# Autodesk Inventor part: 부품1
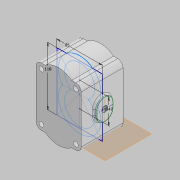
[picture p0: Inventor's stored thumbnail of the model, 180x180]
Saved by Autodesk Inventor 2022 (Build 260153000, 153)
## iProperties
Created: 2023-06
Part Number: 부품1
Material: 일반
Document SubType Name: Modeling
Designer: PC-04
Density: 1 g/cm^3
Appearance: 기본값
Author: PC-04
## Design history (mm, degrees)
sketch "스케치1"
  geometry: L1 (42.5, -55)-(-42.5, -55); L2 (-42.5, -55)-(-42.5, 55); L3 (-42.5, 55)-(42.5, 55); L4 (42.5, 55)-(42.5, -55); L5 (42.5, -55)-(-42.5, 55); L6 (-42.5, -55)-(42.5, 55); L7 (0, 55)-(0, -55); L8 (-42.5, 0)-(42.5, 0); A1 r 28.5 centre (0, 23.5) between (16.125, 0) and (-16.125, 0); A2 r 28.5 centre (0, -23.5) between (-16.125, 0) and (16.125, 0); A3 r 40 centre (0, 23.5) between (32.369, 0) and (-32.369, 0); A4 r 40 centre (0, -23.5) between (-32.369, 0) and (32.369, 0); 5 further points
  constraints: 16 end point, 8 point on circle, 6 midpoint, 4 centre point, 2 coincident, 2 parallel, 2 point on line, 1 horizontal, 1 perpendicular, 1 symmetric about line
  dimensions: "d1" = 85 distance of L2.end L3.end; "d2" = 110 distance of L1.end L2.end; "d7" = 47 diameter of A1.centre L8
extrude "돌출1" new body sketch "스케치1" stored distance "d10" = 79; taper "d11" = 0 deg
fillet "모깎기1" dims "d22" = 10
sketch "스케치5"
  geometry: L1 (32.5, -45)-(-32.5, -45); L2 (-32.5, -45)-(-32.5, 45); L3 (-32.5, 45)-(32.5, 45); L4 (32.5, 45)-(32.5, -45); L5 (32.5, -45)-(-32.5, 45); L6 (-32.5, -45)-(32.5, 45); 1 further point
  constraints: 12 end point, 2 midpoint, 2 parallel, 1 horizontal, 1 perpendicular
  dimensions: "d23" = 65 distance of L2.end L3.end; "d24" = 90 distance of L1.end L2.end
hole "구멍1" sketch "스케치5" at (32.5, -45), (-32.5, -45), (-32.5, 45), (32.5, 45) diameter "d25" = 9; stored, may be unused: countersink angle "d29" = 90 deg, drill point angle "d31" = 118 deg; dims "d26" = 10, "d27" = 4, "d28" = 2, "d30" = 40
sketch "스케치6"
  geometry: L1 (0, 0)-(79, 0) reference; L2 (0, 0)-(79, 0) reference; L3 (39.5, -90)-(39.5, 0); L4 (0, 0)-(79, 0) reference; L5 (39.5, -50)-(39.5, -40); L6 (54.5, -50)-(54.5, -40); L7 (24.5, -40)-(24.5, -50); L8 (79, 0)-(79, -90) reference; L9 (0, -90)-(79, -90) reference; L10 (0, -90)-(0, 0) reference; L11 (79, 0)-(79, -90) reference; L12 (0, -90)-(79, -90) reference; L13 (0, -90)-(0, 0) reference; A1 r 15 centre (39.5, -50) between (24.5, -50) and (54.5, -50); A2 r 15 centre (39.5, -40) between (54.5, -40) and (24.5, -40); 4 further points; 1 other entity
  constraints: 10 end point, 4 point on circle, 4 tangent, 3 midpoint, 2 centre point, 1 parallel, 1 point on line, 2 other
  dimensions: "d32" = 30 distance between parallel lines of L6 L7; "d33" = 10 distance of L5.start L5.end
extrude "돌출6" join sketch "스케치6" distance "d34" = 5; taper "d35" = 0 deg
sketch "스케치8"
  geometry: L1 (24.5, -40)-(24.5, -50) reference; L2 (24.5, -45)-(54.5, -45); L3 (54.5, -40)-(54.5, -50) reference; L4 (39.5, -25)-(39.5, -65); A1 r 15 centre (39.5, -40) between (54.5, -40) and (24.5, -40) reference; A2 r 15 centre (39.5, -50) between (24.5, -50) and (54.5, -50) reference; 2 further points
  constraints: 4 end point, 3 midpoint, 2 point on circle, 1 perpendicular
hole "구멍3" sketch "스케치8" diameter "d43" = 10.5; stored, may be unused: countersink angle "d49" = 90 deg, drill point angle "d51" = 0 deg; dims "d44" = 11, "d45" = 0.62479, "d46" = 10.589, "d47" = 4, "d48" = 2, "d50" = 17.5
fillet "모깎기2" dims "d52" = 3
node "작업 평면2"
node "솔리드1"
mirror "미러1"
node "절단 모서리 투영3"
node "절단 모서리 투영4"
feature "A9D066F2-1C7D-4E18-AEED-F7BC21143FA4" dims "d25" = 9, "d26" = 10, "d27" = 4, "d28" = 2, "d29" = 90 deg, "d30" = 40, "d31" = 118 deg
other parameters: "d5" = 57
